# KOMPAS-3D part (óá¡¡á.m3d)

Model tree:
1. Эскиз:3
2. Листовое тело:2
     Расстояние 1 = 54; Расстояние 2 = 54
3. Эскиз:19
4. Сгиб по эскизу:10
     Толщина листового тела = 2; Ширина освобождения сгиба = 2; Глубина освобождения сгиба = 1; Ширина 1 = 10; Ширина 2 = 10
5. Сгиб(1) - Сгиб по эскизу:10
     Радиус сгиба = 1; Коэффициент = 0.4; Величина сгиба = 10
6. Эскиз:20
7. Сгиб по эскизу:11
     Толщина листового тела = 2; Ширина освобождения сгиба = 2; Глубина освобождения сгиба = 1; Ширина 1 = 10; Ширина 2 = 10
8. Сгиб(1) - Сгиб по эскизу:11
     Радиус сгиба = 1; Коэффициент = 0.4; Величина сгиба = 10
9. Эскиз:21
10. Сгиб по эскизу:12
     Толщина листового тела = 2; Ширина освобождения сгиба = 2; Глубина освобождения сгиба = 1; Ширина 1 = 10; Ширина 2 = 10
11. Сгиб(1) - Сгиб по эскизу:12
     Радиус сгиба = 1; Коэффициент = 0.4; Величина сгиба = 10
12. Эскиз:22
13. Сгиб по эскизу:13
     Толщина листового тела = 2; Ширина освобождения сгиба = 2; Глубина освобождения сгиба = 1; Ширина 1 = 10; Ширина 2 = 10
14. Сгиб(1) - Сгиб по эскизу:13
     Радиус сгиба = 1; Коэффициент = 0.4; Величина сгиба = 10
15. Эскиз:23
16. Операция выдавливания:3
     Расстояние 1 = 0.5; Расстояние 2 = 67
17. Эскиз:24
18. Операция выдавливания:4
     Расстояние 1 = 89; Расстояние 2 = 67
19. Эскиз:25
20. Сгиб по эскизу:14
     Толщина листового тела = 2; Ширина освобождения сгиба = 2; Глубина освобождения сгиба = 1; Ширина 1 = 10; Ширина 2 = 10
21. Сгиб(1) - Сгиб по эскизу:14
     Радиус сгиба = 1; Коэффициент = 0.4; Величина сгиба = 10
22. Эскиз:26
23. Сгиб по эскизу:15
     Толщина листового тела = 2; Ширина освобождения сгиба = 2; Глубина освобождения сгиба = 1; Ширина 1 = 10; Ширина 2 = 10
24. Сгиб(1) - Сгиб по эскизу:15
     Радиус сгиба = 1; Коэффициент = 0.4; Величина сгиба = 10
25. Эскиз:27
26. Вырезать элемент выдавливания:7
     Расстояние 1 = 176

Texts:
  stalker61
